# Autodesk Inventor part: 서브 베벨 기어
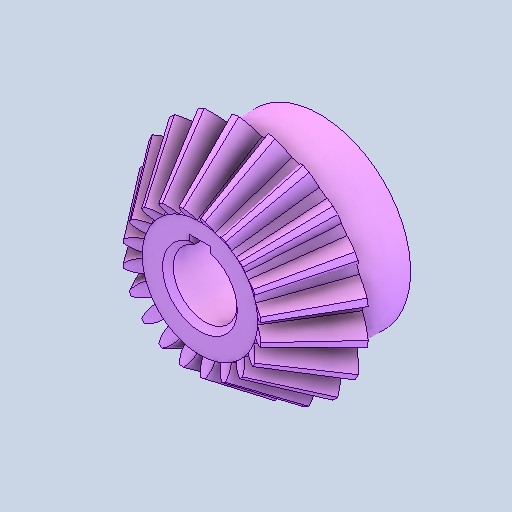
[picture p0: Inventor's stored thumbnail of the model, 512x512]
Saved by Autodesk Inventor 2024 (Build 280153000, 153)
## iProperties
Created: 2026-07
Part Number: 서브 베벨 기어
Material: 강철, 합금
Document SubType Name: Modeling
Designer: com
Density: 7.73 g/cm^3
Appearance: 기본값
Author: jhkim
Revision Number: 1
Sending System: Autodesk Inventor 2027
Preprocessor: ST-DEVELOPER v20.1
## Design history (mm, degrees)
node "서브 베벨기어1"
  node "스케치11"
node "스케치10"
node "솔리드1"
body "Solid1"
